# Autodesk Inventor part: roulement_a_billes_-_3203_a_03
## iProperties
Shininess: 64.0
Length Units: 11269
Angle Units: 11279
Time Units: 11290
Mass Units: 11283
Length Display Precision: 3
Angle Display Precision: 2
Compacted: True
Part Number: roulement_a_billes_-_3203_a_03
Document SubType Name: Modeling
Created: 2005-02
Material: Par défaut
Designer: LEGERET Philippe
Density: 0.0
Volumn: 0.0
Area: 0.0
PropertySet Name: Model Information
Control State: 0
Master: False
Checked Out: False
Author: LEGERET Philippe
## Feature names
1. Base1
